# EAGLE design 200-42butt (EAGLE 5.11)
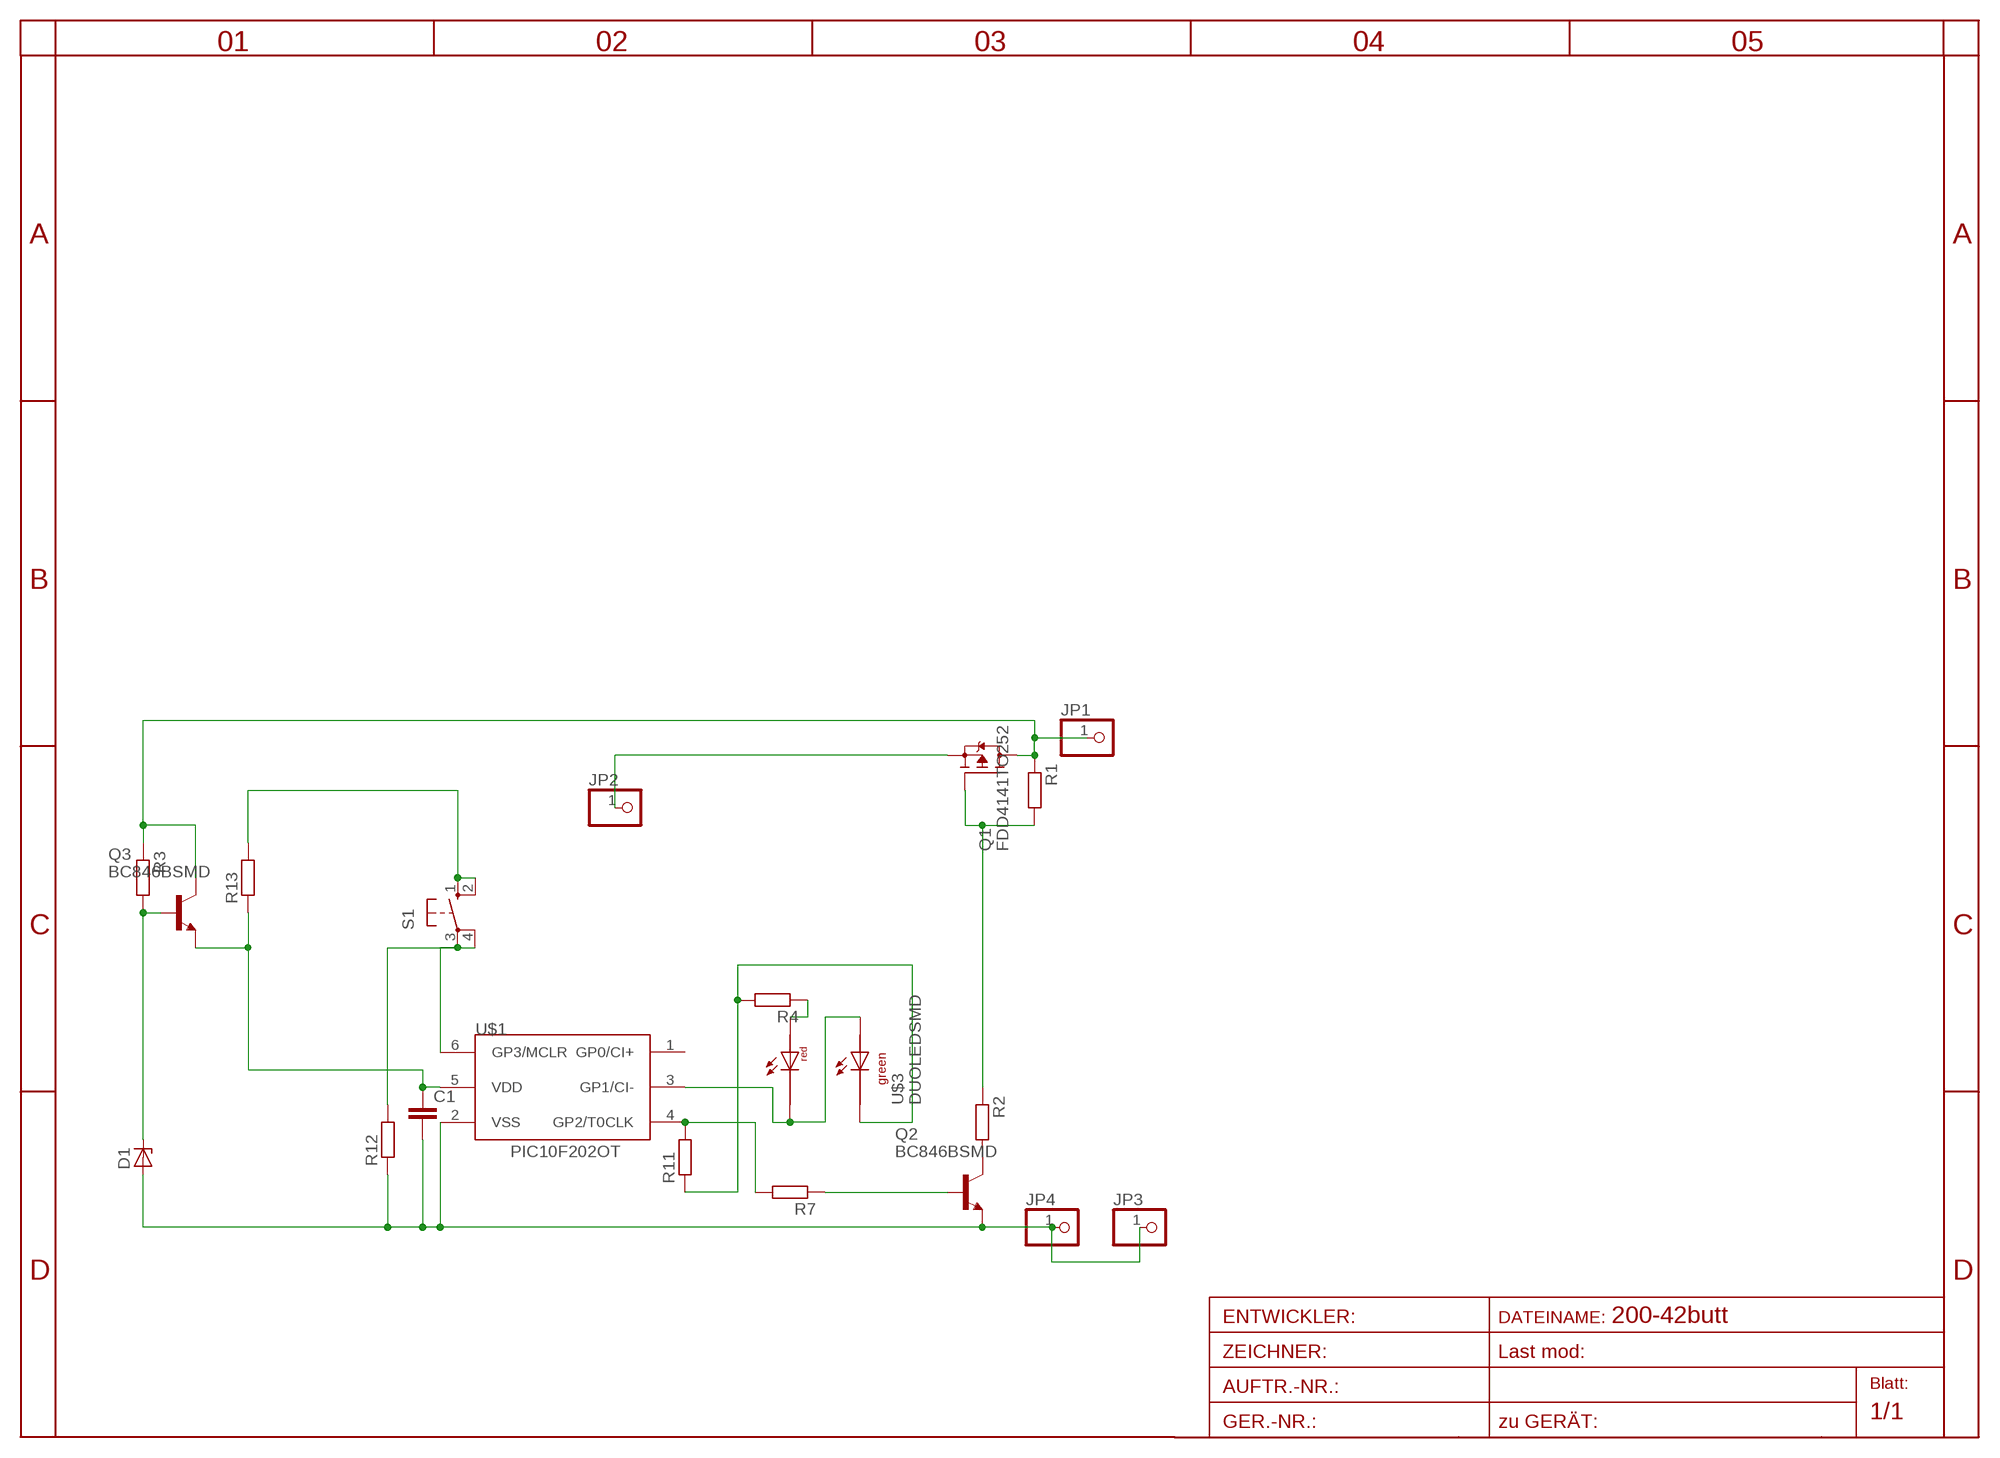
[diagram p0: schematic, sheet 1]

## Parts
C1  C-EUC1206  [C1206]
D1  ZENER-DIODESOD80C  [SOD80C]
JP1  PINHD-1X11MM6  [1X1MM8]
JP2  PINHD-1X11MM6  [1X1MM8]
JP3  PINHD-1X11MM6  [1X1MM8]
JP4  PINHD-1X11MM6  [1X1MM8]
Q1  FDD4141TO252  [TO252]
Q2  BC846BSMD  [SOT23]
Q3  BC846BSMD  [SOT23]
R1  R-EU_R0805  [R0805]
R2  R-EU_R0805  [R0805]
R3  R-EU_R0805  [R0805]
R4  R-EU_R0805  [R0805]
R7  R-EU_R1206  [R1206]
R11  R-EU_R0805  [R0805]
R12  R-EU_R0805  [R0805]
R13  R-EU_R0805  [R0805]
S1  10-XX  [B3F-10XX]
U$1  PIC10F202OT  [SOT23-6]
U$3  DUOLEDSMD  [DUOLEDSMD]

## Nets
GND: C1.2 D1.A JP3.1 JP4.1 Q2.2(E) R12.1 U$1.2(VSS)
GP2: R7.2 R11.2 U$1.4(GP2/T0CLK)
GP3: R12.2 S1.3(P) S1.4(P1) U$1.6(GP3/MCLR)
N$2: U$1.3(GP1/CI-) U$3.AGRN U$3.CRED
N$3: Q2.3(C) R2.2
N$4: D1.C Q3.1(B) R3.2
N$5: R4.1 U$3.ARED
N$6: R4.2 R11.1 U$3.CGRN
N$7: Q1.1(G) R1.2 R2.1
N$10: Q2.1(B) R7.1
N$15: R13.2 S1.1(S) S1.2(S1)
V+IN: JP1.1 Q1.2(D) Q3.3(C) R1.1 R3.1
V+OUT: JP2.1 Q1.3(S)
VDD: C1.1 Q3.2(E) R13.1 U$1.5(VDD)
Unconnected: U$1.1(GP0/CI+)

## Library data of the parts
C1 = rcl:C-EU: CAPACITOR, European symbol
D1 = diode-1:ZENER-DIODE: Z-Diode
JP1-JP4 = pinhead:PINHD-1X1: PIN HEADER
Q1 = transistor-fet:FDD4141: P-Channel PowerTrench® MOSFET Source: FDD4141.pdf
Q2 Q3 = transistor-npn:BC846*: NPN Transistor
R1-R4 R7 R11-R13 = rcl:R-EU_: RESISTOR, European symbol
S1 = switch-omron:10-XX: OMRON SWITCH
U$1 = microchip-5:PIC10F2*: uPC nW 0,25/0,5k Program Flash memory Comparator
U$3 = led:DUOLEDSMD

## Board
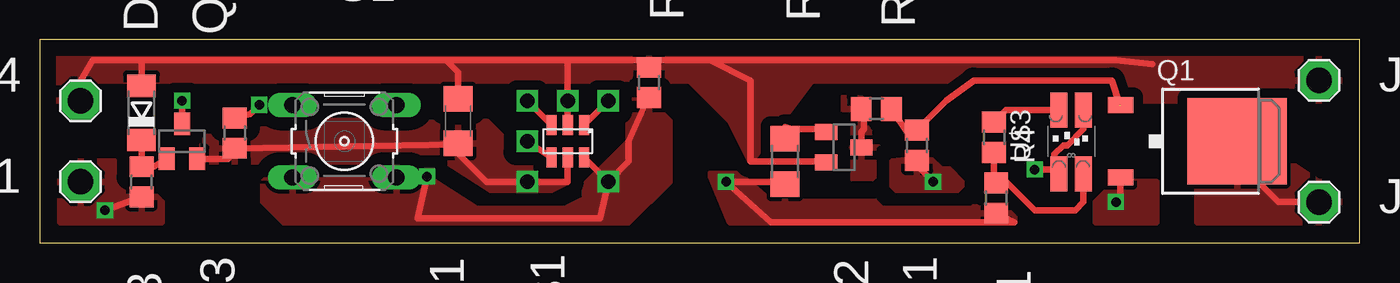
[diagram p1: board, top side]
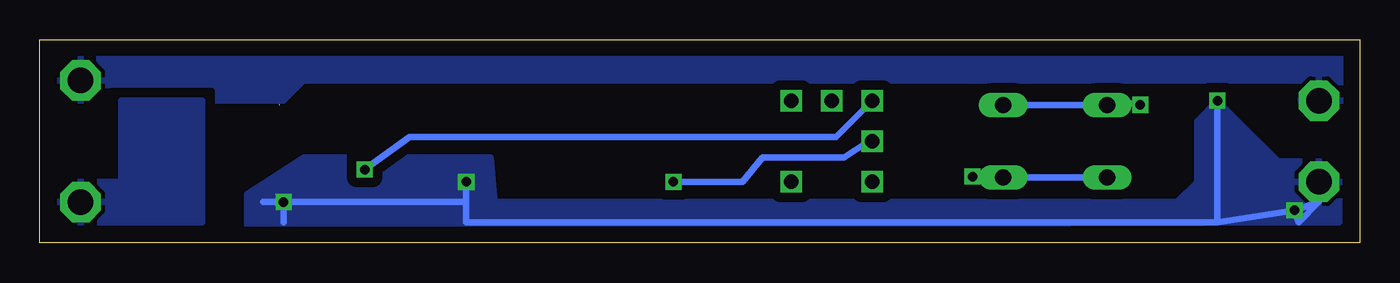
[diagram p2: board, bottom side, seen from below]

Size 82.55 x 12.7 mm. Coordinates in mm from the lower left corner, seen from the top.
Outline: 0,0 82.55,0 82.55,12.7 0,12.7 0,0
Copper layers (1*16): Top 0.035mm / dielectric 1.5mm / Bottom 0.035mm
Design rules "default": minimum track width 10mil, minimum drill 24mil, track to track 8mil, track to pad 8mil, pad to pad 8mil, via to via 8mil, smd to smd 8mil, copper to edge 40mil, drill to drill 8mil, minimum pad ring 10mil, minimum via ring 8mil, stop-mask expansion 4mil, vias tented up to drill 0mil, thermal gap 10mil

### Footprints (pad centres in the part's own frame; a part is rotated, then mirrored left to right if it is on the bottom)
C1206 = smd 1.6 x 1.8: 1 -1.4,0; 2 1.4,0
SOD80C = smd 1.4 x 1.8: A 1.7,0; C -1.7,0
1X1MM8 = drill 1.6 pad 2.54 octagon: 1 0,0
TO252 = smd 1 x 1.6: 1 -2.28,-4.8; 2 2.28,-4.8 | smd 5.4 x 6.2: 3 0,2.5
SOT23 = smd 1 x 1.4: 1 -0.95,-1.1; 2 0.95,-1.1; 3 0,1.1
R0805 = smd 1.3 x 1.5: 1 -0.95,0; 2 0.95,0
R1206 = smd 1.6 x 1.803: 1 -1.422,0; 2 1.422,0
B3F-10XX = drill 1.016 long: 1 -3.251,2.261; 2 3.251,2.261; 3 -3.251,-2.261; 4 3.251,-2.261
SOT23-6 = smd 0.635 x 1.27: 1 -1.016,-1.016; 2 0,-1.016; 3 1.016,-1.016; 4 1.016,1.016; 5 0,1.016; 6 -1.016,1.016
DUOLEDSMD = smd 1.067 x 2.184: AGRN 0.77,1.95; ARED -0.77,1.95; CGRN 0.77,-2.05; CRED -0.77,-2.05

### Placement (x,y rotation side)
C1  26.16,7.62 90 top
D1  6.35,8.13 90 top
JP1  2.54,3.81 0 top
JP2  80.01,2.54 0 top
JP3  80.01,10.16 0 top
JP4  2.54,8.89 0 top
Q1  72.39,6.35 270 top
Q2  50.29,5.97 270 top
Q3  8.89,6.35 0 top
R1  54.86,6.1 90 top
R2  52.32,8.38 180 top
R3  6.35,3.81 90 top
R4  59.69,6.6 270 top
R7  46.61,5.08 270 top
R11  59.82,2.79 270 top
R12  38.1,10.03 270 top
R13  12.19,6.86 90 top
S1  19.05,6.35 0 top
U$1  33.02,6.35 180 top
U$3  64.52,6.35 0 top

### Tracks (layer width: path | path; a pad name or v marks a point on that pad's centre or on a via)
GND  (via drill 0.9 pad 1.27)
  Top 0.406: U$1.2 v33.02,8.89 33.02,11.43 | D1.A 6.35,11.43 | 6.35,11.43 3.3,11.43 2.54,10.16 | C1.2 26.16,10.67 25.4,11.43 | 6.35,11.43 25.4,11.43 | 25.4,11.43 33.02,11.43 | Q2.2 48.45,5.08 44.45,5.08 44.45,10.16 41.91,11.43 | 33.02,11.43 38.1,11.43 | 38.1,11.43 41.91,11.43 | 69.6,11.18 67.31,11.43 41.91,11.43 | 38.1,11.43 R12.1
  pour Top (isolate 0.61, rank 3): 0,7.62 0,11.43 3.81,12.7 68.58,12.7 81.28,11.43 81.28,8.89 67.31,8.89 66.04,10.16 48.26,10.16 44.45,5.08 43.18,7.62 40.64,10.16 3.81,10.16 3.56,7.87
  pour Bottom (isolate 0.61, rank 3): 0,7.62 0,11.43 3.81,12.7 68.58,12.7 81.28,11.43 81.28,8.89 67.31,8.89 66.04,10.16 40.64,10.16 3.81,10.16 3.56,7.87
GP2  (via drill 0.6, 0.9 pad 1.27)
  Top 0.406: R11.2 60.96,1.27 45.72,1.27 v42.93,3.81 46,3.81 R7.2 | U$1.4 v30.48,6.35
  Bottom 0.406: v42.93,3.81 38.61,3.81 37.34,5.33 32.26,5.33 30.73,6.35 v30.48,6.35 30.48,6.1
  pour Top (isolate 0.813, rank 2): 43.69,4.32 41.91,4.32 43.18,1.27 60.96,1.27 60.96,2.54 45.72,2.54
GP3  (via drill 0.6, 0.9 pad 1.27)
  Top 0.406: v35.56,3.81 35.56,4.26 35.11,4.26 U$1.6 | v24.21,4.14 23.62,1.52 35.05,1.52 v35.56,3.81 | R12.2 37.85,8.64 36.83,6.35 36.83,5.08 v35.56,3.81
  Bottom 0.406: v24.21,4.14 S1.4 S1.3
  pour Top (isolate 0.813, rank 2): 13.97,3.81 13.97,2.54 15.24,1.27 36.83,1.27 39.37,3.81 39.37,7.62 38.1,8.89 36.83,8.89 36.83,6.35 33.02,2.54 27.94,2.54 25.4,5.08 15.24,5.08
N$1  (via drill 0.9 pad 1.27)
  Top 0.406: 34.29,7.62 v35.56,8.89
N$2  (via drill 0.6, 0.9)
  Top 0.406: U$1.3 v30.48,8.89 | v62.23,4.57 63.47,4.57 | 63.47,4.57 U$3.CRED | 63.47,4.57 63.47,5.56 64.01,6.1 64.26,6.1 65.28,7.11 65.28,8.29 U$3.AGRN
  Bottom 0.406: v30.48,8.89 32.77,6.6 59.44,6.6 v62.23,4.57
N$3
  Top 0.406: Q2.3 51.39,6.94 51.56,7.11 51.56,8.06 R2.2
  pour Top (isolate 0.813, rank 2): 52.07,8.89 51.82,8.89 50.8,9.14 50.29,9.14 50.29,4.57 50.8,4.06 52.07,4.06 52.58,4.57
N$4
  Top 0.406: D1.C R3.2 7.16,4.76 Q3.1
N$5
  Top 0.406: U$3.ARED 60.44,8.3 R4.1
N$6
  Top 0.406: U$3.CGRN 65.28,4.29 65.28,2.54 64.77,2.03 62.23,2.03 60.52,3.74 R11.1 59.69,3.87 R4.2
N$7  (1 unrouted)
  Top 0.406: R2.1 54.29,6.82 R1.2 56.71,8.89 58.42,10.16 67.06,10.16 67.57,8.63
N$10
  Top 0.406: R7.1 46.61,7.24 46.99,7.11 48.49,7.11 Q2.1
N$15  (via drill 0.6)
  Top 0.406: R13.2 13.14,8.06 v13.72,8.64
  Bottom 0.406: v13.72,8.64 15.52,8.89 S1.1 S1.2
V+IN  (via drill 0.6)
  Top 0.406: v8.89,8.89 Q3.3 | v4.06,2.03 R3.1 | R1.1 54.86,4.83 v55.88,3.81 | Q1.2 67.59,2.82 v67.31,2.54
  Bottom 0.406: 2.54,2.54 3.81,1.27 v4.06,2.03 | v4.06,2.03 8.89,1.27 | 8.89,1.27 55.88,1.27 55.88,2.54 | 8.89,1.27 v8.89,8.89 | v4.06,2.03 2.54,2.54 | 2.54,2.54 JP1.1 | 55.88,2.54 v55.88,3.81 | 55.88,2.54 v67.31,2.54 | v67.31,2.54 68.58,2.54 | v67.31,2.54 67.31,1.27
  pour Bottom (isolate 0.61): 1.27,5.08 5.08,5.08 8.89,8.89 10.16,7.62 10.16,3.81 11.43,2.54 54.1,2.54 54.36,5.33 66.04,5.33 69.6,3.05 69.6,1.02 68.58,1.02 1.27,1.27
  pour Top (isolate 0.813): 53.34,5.08 53.34,3.81 53.34,3.56 53.59,3.3 57.4,3.3 57.66,3.56 57.66,3.81 56.9,4.57 56.39,4.57 55.63,5.33
  pour Top (isolate 0.813): 1.27,5.08 5.08,5.08 7.62,2.54 7.62,1.27 1.27,1.27
  pour Top: 69.85,3.81 69.85,1.27 66.04,1.27 66.04,2.54 67.31,3.81
V+OUT
  Top 0.406: JP2.1 77.47,2.54 74.93,5.08 74.93,6.31 Q1.3
  pour Bottom: 77.47,3.81 81.28,3.81 81.28,1.27 72.39,1.27 72.39,8.89 77.47,8.89
  pour Top: 80.01,3.81 81.28,3.81 81.28,1.27 72.39,1.27 72.39,5.08 73.66,6.35 76.2,6.35
VDD  (via drill 0.9 pad 1.27)
  Top 0.406: Q3.2 11.79,5.25 R13.1 26.1,6.16 C1.1 26.16,5.59 27.94,3.81 v30.48,3.81 33.02,3.81 U$1.5
  pour Top (isolate 0.813): 10.16,6.35 11.43,7.62 27.94,7.62 30.48,5.08 31.75,5.08 33.02,3.81 32,3.3 28.19,3.3 25.4,5.08 10.16,5.08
